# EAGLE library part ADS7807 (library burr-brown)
Low-Power 16-Bit Sampling CMOS ADC
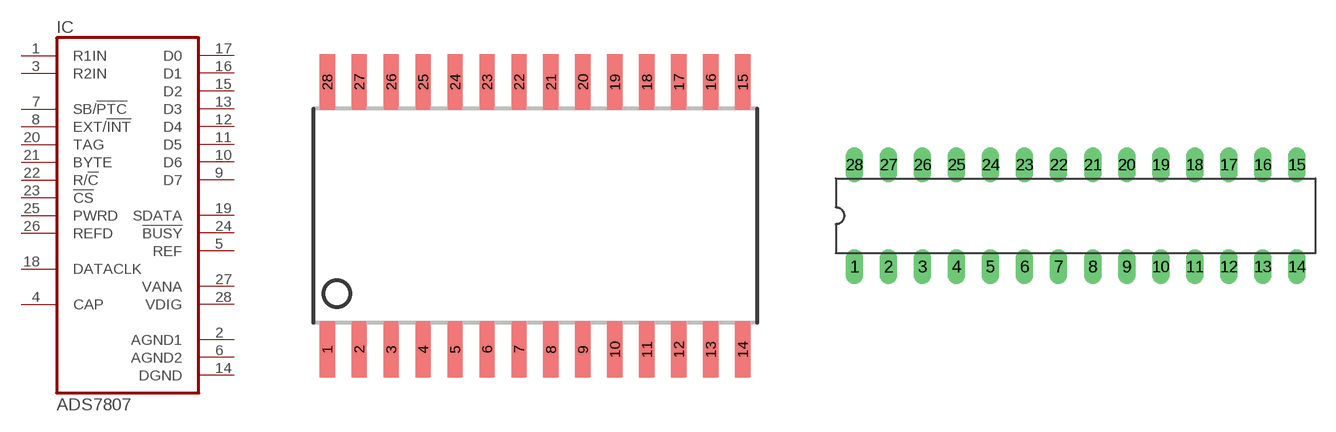
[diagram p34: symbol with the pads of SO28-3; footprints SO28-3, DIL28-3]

Designator prefix IC

## ADS7807U (MF: TEXAS INSTRUMENTS; MPN: ADS7807U; OC_FARNELL: 1273123; OC_NEWARK: 80K5548)  [SO28-3]
1  R1IN  in
2  AGND1  pwr
3  R2IN  in
4  CAP  pas
5  REF  out
6  AGND2  pwr
7  SB/!PTC  in
8  EXT/!INT  in
9  D7  out
10  D6  out
11  D5  out
12  D4  out
13  D3  out
14  DGND  pwr
15  D2  out
16  D1  out
17  D0  out
18  DATACLK
19  SDATA  out
20  TAG  in
21  BYTE  in
22  R/!C  in
23  !CS  in
24  !BUSY  out
25  PWRD  in
26  REFD  in
27  VANA  pwr
28  VDIG  pwr

## ADS7807P (MF: TEXAS INSTRUMENTS; MPN: ADS7807P; OC_FARNELL: 1097549; OC_NEWARK: 74C7075)  [DIL28-3]
Pads as for SO28-3

## Footprint SO28-3 (pad centres in mm)
Small Outline Package
smd 0.61 x 2.21: 1 -8.255,-5.315; 2 -6.985,-5.315; 3 -5.715,-5.315; 4 -4.445,-5.315; 5 -3.175,-5.315; 6 -1.905,-5.315; 7 -0.635,-5.315; 8 0.635,-5.315; 9 1.905,-5.315; 10 3.175,-5.315; 11 4.445,-5.315; 12 5.715,-5.315; 13 6.985,-5.315; 14 8.255,-5.315; 15 8.255,5.315; 16 6.985,5.315; 17 5.715,5.315; 18 4.445,5.315; 19 3.175,5.315; 20 1.905,5.315; 21 0.635,5.315; 22 -0.635,5.315; 23 -1.905,5.315; 24 -3.175,5.315; 25 -4.445,5.315; 26 -5.715,5.315; 27 -6.985,5.315; 28 -8.255,5.315

## Footprint DIL28-3 (pad centres in mm)
Dual In Line 0.3 inch
drill 0.813 long: 1 -16.51,-3.81; 2 -13.97,-3.81; 3 -11.43,-3.81; 4 -8.89,-3.81; 5 -6.35,-3.81; 6 -3.81,-3.81; 7 -1.27,-3.81; 8 1.27,-3.81; 9 3.81,-3.81; 10 6.35,-3.81; 11 8.89,-3.81; 12 11.43,-3.81; 13 13.97,-3.81; 14 16.51,-3.81; 15 16.51,3.81; 16 13.97,3.81; 17 11.43,3.81; 18 8.89,3.81; 19 6.35,3.81; 20 3.81,3.81; 21 1.27,3.81; 22 -1.27,3.81; 23 -3.81,3.81; 24 -6.35,3.81; 25 -8.89,3.81; 26 -11.43,3.81; 27 -13.97,3.81; 28 -16.51,3.81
